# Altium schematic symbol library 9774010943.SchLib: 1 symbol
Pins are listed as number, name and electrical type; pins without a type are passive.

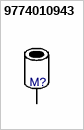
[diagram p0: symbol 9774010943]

## 9774010943
designator M?
PartNumer: 9774010943; Manufacturer: Wurth Elektronik
pins: 1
